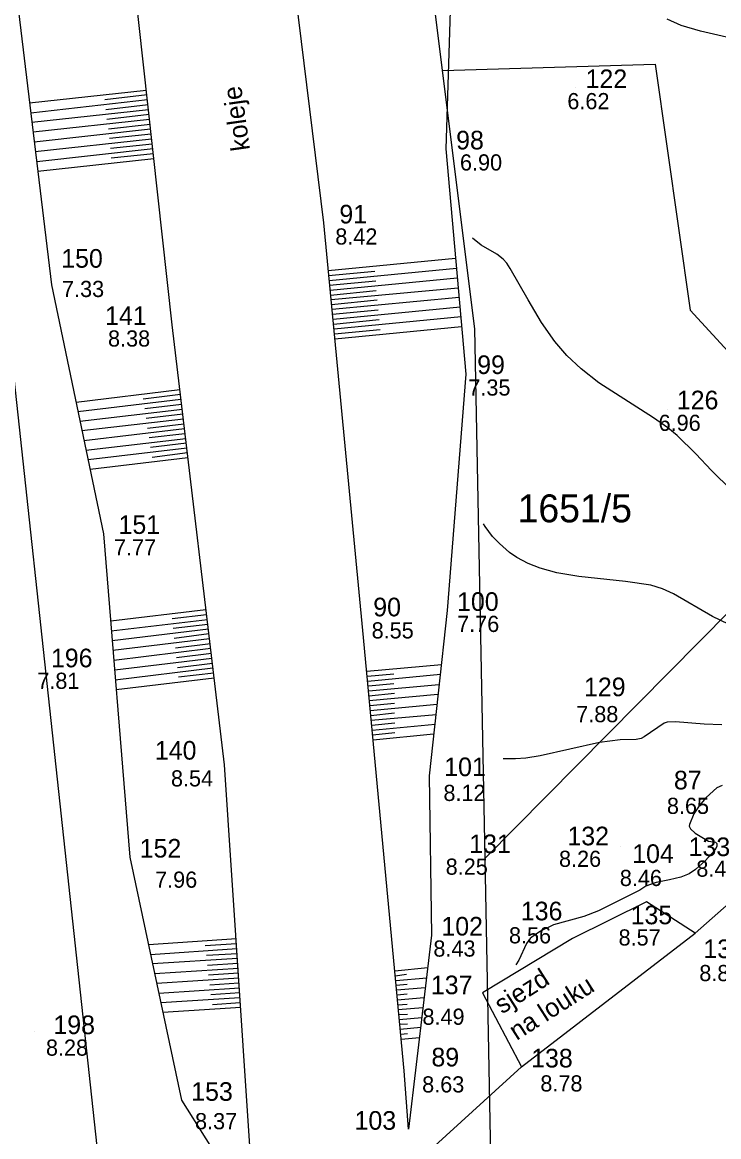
# Model space of a CAD drawing. Extents: x -792549 to -792339, y -1111914 to -1111617.
# Drawn here: x -792471.21 to -792457.02, y -1111705.97 to -1111683.25 of the extents above; entities that cross this region are included whole.
import ezdxf

# ---------------------------------------------------------------- set-up
doc = ezdxf.new("R2010")
doc.units = 0
for name, color, linetype in [('Vrstva 1', 7, 'Continuous'), ('Vrstva 32', 7, 'Continuous'), ('Vrstva 33', 7, 'Continuous'), ('Vrstva 41', 7, 'Continuous'), ('Vrstva 42', 7, 'Continuous'), ('Vrstva 45', 7, 'Continuous'), ('Vrstva 46', 7, 'Continuous'), ('Vrstva 48', 7, 'Continuous'), ('Vrstva 49', 7, 'Continuous'), ('Vrstva 50', 7, 'Continuous'), ('Vrstva 52', 7, 'Continuous'), ('Vrstva 54', 7, 'Continuous')]:
    doc.layers.add(name, color=color, linetype=linetype)

# ---------------------------------------------------------------- blocks, each defined once
blk = doc.blocks.new('SC6231')
at = {"layer": 'Vrstva 1'}
blk.add_line((0, 0), (0, 0), dxfattribs=at)

msp = doc.modelspace()

# ---------------------------------------------------------------- linework, layer by layer
at = {"layer": 'Vrstva 32'}
for points in [[(-792456.756, -1111692.789), (-792457.164, -1111692.387), (-792457.485, -1111692.05), (-792457.861, -1111691.674), (-792458.052, -1111691.514), (-792458.347, -1111691.313), (-792459.458, -1111690.601), (-792459.824, -1111690.317), (-792460.113, -1111690.042), (-792460.358, -1111689.755), (-792460.63, -1111689.369), (-792460.905, -1111688.91), (-792461.268, -1111688.265), (-792461.337, -1111688.156), (-792461.409, -1111688.076), (-792461.538, -1111687.979), (-792461.861, -1111687.792), (-792462.038, -1111687.652)], [(-792456.956, -1111697.572), (-792457.311, -1111697.56), (-792457.898, -1111697.511), (-792458.067, -1111697.521), (-792458.13, -1111697.541), (-792458.534, -1111697.815), (-792458.601, -1111697.849), (-792458.699, -1111697.869), (-792459.027, -1111697.876), (-792459.445, -1111697.931), (-792460.658, -1111698.206), (-792460.951, -1111698.252), (-792461.157, -1111698.268), (-792461.413, -1111698.265)]]:
    msp.add_lwpolyline(points, dxfattribs=at)
at = {"layer": 'Vrstva 33'}
for points in [[(-792456.593, -1111683.613), (-792457.386, -1111683.428), (-792457.783, -1111683.31), (-792458.07, -1111683.186)], [(-792456.816, -1111695.519), (-792457.146, -1111695.362), (-792457.939, -1111694.903), (-792458.164, -1111694.797), (-792458.402, -1111694.727), (-792458.915, -1111694.652), (-792459.87, -1111694.547), (-792460.314, -1111694.471), (-792460.66, -1111694.379), (-792460.904, -1111694.283), (-792461.135, -1111694.161), (-792461.28, -1111694.057), (-792461.486, -1111693.877), (-792461.626, -1111693.73), (-792461.781, -1111693.529), (-792461.811, -1111693.478)], [(-792456.944, -1111698.808), (-792457.052, -1111698.855), (-792457.273, -1111699.054), (-792457.416, -1111699.222), (-792457.522, -1111699.386), (-792457.615, -1111699.603), (-792457.617, -1111699.637), (-792457.592, -1111699.694), (-792457.499, -1111699.78), (-792457.226, -1111699.947), (-792457.08, -1111699.965), (-792457.057, -1111699.99), (-792457.052, -1111700.053), (-792457.099, -1111700.13), (-792457.293, -1111700.348), (-792457.487, -1111700.524), (-792457.618, -1111700.61), (-792457.787, -1111700.681), (-792458.023, -1111700.737), (-792458.289, -1111700.786), (-792458.503, -1111700.865), (-792458.623, -1111700.948), (-792459.467, -1111701.364), (-792459.765, -1111701.483), (-792460.385, -1111701.654), (-792460.651, -1111701.783), (-792460.83, -1111701.903), (-792460.859, -1111701.93), (-792460.936, -1111702.034), (-792461.09, -1111702.37), (-792461.153, -1111702.466)]]:
    msp.add_lwpolyline(points, dxfattribs=at)
at = {"layer": 'Vrstva 41'}
for points in [[(-792462.65, -1111684.23), (-792470.12, -1111624.156)], [(-792396.21, -1111631.51), (-792404.9, -1111639.66), (-792454.29, -1111692.72), (-792461.78, -1111700.29), (-792461.99, -1111689.5), (-792462.65, -1111684.23), (-792458.31, -1111684.1), (-792457.6, -1111689.12), (-792454.29, -1111692.72)], [(-792472.48, -1111680.42), (-792469.49, -1111708.06), (-792472.44, -1111711.74), (-792473.08, -1111699.31), (-792481.68, -1111682.99)], [(-792468.11, -1111720.8), (-792467.76, -1111724.02), (-792461.41, -1111719.58), (-792461.78, -1111700.29)]]:
    msp.add_lwpolyline(points, dxfattribs=at)
at = {"layer": 'Vrstva 46'}
for points in [[(-792466.48, -1111707.59), (-792467.09, -1111698.39), (-792468.16, -1111689.42), (-792468.94, -1111682.32), (-792469.82, -1111674.62), (-792470.64, -1111665.94), (-792471.65, -1111658.95)], [(-792474.58, -1111659.1), (-792474.14, -1111664.3), (-792473.03, -1111672.63), (-792471.62, -1111680.31), (-792470.62, -1111688.6), (-792469.56, -1111693.68), (-792469.02, -1111700.27), (-792467.97, -1111705.23), (-792466.48, -1111707.59)], [(-792464.38, -1111663.08), (-792463.28, -1111670.4), (-792462.69, -1111676.81), (-792462.46, -1111681.92), (-792462.58, -1111685.83), (-792462.17, -1111690.42), (-792462.55, -1111695.24), (-792462.92, -1111698.61), (-792462.87, -1111701.86), (-792463.34, -1111705.82)], [(-792463.34, -1111705.82), (-792463.43, -1111704.63), (-792464.27, -1111695.65), (-792465.07, -1111687.34), (-792466.27, -1111677.56), (-792467.145, -1111670.547), (-792468.021, -1111663.535)], [(-792457.5, -1111701.82), (-792458.49, -1111701.18), (-792460, -1111701.93), (-792461.83, -1111703.04), (-792461.04, -1111704.55)]]:
    msp.add_lwpolyline(points, dxfattribs=at)
at = {"layer": 'Vrstva 52'}
msp.add_line((-792461.04, -1111704.55), (-792457.5, -1111701.82), dxfattribs=at)
for points in [[(-792430.84, -1111675.46), (-792443.34, -1111688.31), (-792451.9, -1111696.88), (-792457.5, -1111701.82)], [(-792461.04, -1111704.55), (-792465.57, -1111708.68), (-792470.85, -1111713.69), (-792475, -1111717.97), (-792476.06, -1111719.06), (-792477.52, -1111721.33), (-792480.13, -1111725.28), (-792484.43, -1111732.17), (-792488.75, -1111739.76), (-792492.85, -1111746.66), (-792495.96, -1111751.8)]]:
    msp.add_lwpolyline(points, dxfattribs=at)
at = {"layer": 'Vrstva 54'}
for p, q in [((-792468.69, -1111684.64), (-792471.07, -1111684.9)), ((-792468.67, -1111684.73), (-792469.53, -1111684.83)), ((-792468.66, -1111684.83), (-792471.04, -1111685.1)), ((-792468.65, -1111684.93), (-792469.51, -1111685.03)), ((-792468.64, -1111685.03), (-792471.02, -1111685.29)), ((-792468.63, -1111685.13), (-792469.49, -1111685.23)), ((-792468.62, -1111685.23), (-792470.99, -1111685.49)), ((-792468.61, -1111685.33), (-792469.46, -1111685.43)), ((-792468.6, -1111685.43), (-792470.97, -1111685.69)), ((-792468.58, -1111685.63), (-792470.95, -1111685.89)), ((-792468.59, -1111685.53), (-792469.44, -1111685.62)), ((-792468.55, -1111685.83), (-792470.92, -1111686.09)), ((-792468.57, -1111685.73), (-792469.42, -1111685.82)), ((-792468.53, -1111686.03), (-792470.9, -1111686.29)), ((-792468.54, -1111685.93), (-792469.4, -1111686.02)), ((-792464.98, -1111688.31), (-792462.38, -1111688.06)), ((-792464.97, -1111688.41), (-792464.03, -1111688.32)), ((-792464.96, -1111688.51), (-792462.36, -1111688.26)), ((-792464.95, -1111688.61), (-792464.01, -1111688.52)), ((-792464.94, -1111688.71), (-792462.35, -1111688.46)), ((-792464.93, -1111688.81), (-792464, -1111688.72)), ((-792464.92, -1111688.9), (-792462.33, -1111688.66)), ((-792464.91, -1111689), (-792463.98, -1111688.91)), ((-792464.9, -1111689.1), (-792462.31, -1111688.85)), ((-792464.88, -1111689.3), (-792462.29, -1111689.05)), ((-792464.89, -1111689.2), (-792463.96, -1111689.11)), ((-792464.86, -1111689.5), (-792462.27, -1111689.25)), ((-792464.87, -1111689.4), (-792463.94, -1111689.31)), ((-792464.85, -1111689.6), (-792463.92, -1111689.51)), ((-792464.84, -1111689.7), (-792462.26, -1111689.45)), ((-792468, -1111690.74), (-792470.12, -1111691)), ((-792467.99, -1111690.84), (-792468.75, -1111690.93)), ((-792467.98, -1111690.94), (-792470.08, -1111691.19)), ((-792467.97, -1111691.04), (-792468.72, -1111691.13)), ((-792467.95, -1111691.14), (-792470.04, -1111691.39)), ((-792467.94, -1111691.24), (-792468.69, -1111691.33)), ((-792467.93, -1111691.34), (-792470, -1111691.58)), ((-792467.91, -1111691.54), (-792469.96, -1111691.78)), ((-792467.92, -1111691.44), (-792468.66, -1111691.53)), ((-792467.88, -1111691.74), (-792469.92, -1111691.98)), ((-792467.9, -1111691.64), (-792468.63, -1111691.72)), ((-792467.86, -1111691.93), (-792469.87, -1111692.17)), ((-792467.87, -1111691.83), (-792468.6, -1111691.92)), ((-792467.84, -1111692.13), (-792469.83, -1111692.37)), ((-792467.85, -1111692.03), (-792468.57, -1111692.12)), ((-792467.47, -1111695.23), (-792469.41, -1111695.46)), ((-792467.46, -1111695.33), (-792468.16, -1111695.41)), ((-792467.44, -1111695.43), (-792469.4, -1111695.66)), ((-792467.42, -1111695.62), (-792469.38, -1111695.86)), ((-792467.43, -1111695.53), (-792468.14, -1111695.61)), ((-792467.4, -1111695.82), (-792469.37, -1111696.06)), ((-792467.41, -1111695.72), (-792468.12, -1111695.81)), ((-792467.37, -1111696.02), (-792469.35, -1111696.26)), ((-792467.38, -1111695.92), (-792468.09, -1111696.01)), ((-792467.35, -1111696.22), (-792469.33, -1111696.46)), ((-792467.36, -1111696.12), (-792468.07, -1111696.21)), ((-792467.34, -1111696.32), (-792468.05, -1111696.41)), ((-792467.33, -1111696.42), (-792469.32, -1111696.66)), ((-792467.31, -1111696.52), (-792468.03, -1111696.6)), ((-792464.19, -1111696.48), (-792462.67, -1111696.34)), ((-792464.18, -1111696.58), (-792463.64, -1111696.53)), ((-792464.17, -1111696.68), (-792462.69, -1111696.54)), ((-792467.3, -1111696.62), (-792469.3, -1111696.86)), ((-792464.16, -1111696.78), (-792463.64, -1111696.73)), ((-792464.15, -1111696.88), (-792462.72, -1111696.75)), ((-792464.15, -1111696.98), (-792463.63, -1111696.93)), ((-792464.14, -1111697.08), (-792462.74, -1111696.95)), ((-792464.13, -1111697.18), (-792463.63, -1111697.13)), ((-792464.12, -1111697.28), (-792462.76, -1111697.15)), ((-792464.11, -1111697.38), (-792463.63, -1111697.33)), ((-792464.1, -1111697.48), (-792462.78, -1111697.36)), ((-792464.09, -1111697.58), (-792463.62, -1111697.53)), ((-792464.08, -1111697.68), (-792462.8, -1111697.56)), ((-792464.07, -1111697.78), (-792463.62, -1111697.73)), ((-792464.06, -1111697.88), (-792462.83, -1111697.76)), ((-792466.85, -1111701.94), (-792468.64, -1111702.06)), ((-792466.84, -1111702.14), (-792468.6, -1111702.26)), ((-792466.85, -1111702.04), (-792467.49, -1111702.08)), ((-792466.83, -1111702.24), (-792467.46, -1111702.28)), ((-792466.83, -1111702.34), (-792468.56, -1111702.45)), ((-792466.82, -1111702.44), (-792467.44, -1111702.48)), ((-792466.81, -1111702.54), (-792468.52, -1111702.65)), ((-792466.81, -1111702.64), (-792467.42, -1111702.68)), ((-792463.62, -1111702.59), (-792462.95, -1111702.52)), ((-792463.61, -1111702.69), (-792463.38, -1111702.66)), ((-792466.8, -1111702.74), (-792468.47, -1111702.85)), ((-792466.8, -1111702.84), (-792467.39, -1111702.88)), ((-792463.6, -1111702.79), (-792462.97, -1111702.73)), ((-792463.59, -1111702.88), (-792463.37, -1111702.86)), ((-792466.79, -1111702.94), (-792468.43, -1111703.05)), ((-792466.78, -1111703.14), (-792468.39, -1111703.24)), ((-792466.78, -1111703.04), (-792467.37, -1111703.08)), ((-792463.58, -1111702.98), (-792463, -1111702.93)), ((-792463.57, -1111703.08), (-792463.37, -1111703.06)), ((-792463.57, -1111703.18), (-792463.02, -1111703.13)), ((-792466.76, -1111703.34), (-792468.35, -1111703.44)), ((-792466.77, -1111703.24), (-792467.34, -1111703.28)), ((-792463.56, -1111703.28), (-792463.37, -1111703.27)), ((-792463.55, -1111703.38), (-792463.05, -1111703.34)), ((-792463.54, -1111703.48), (-792463.36, -1111703.47)), ((-792463.53, -1111703.58), (-792463.07, -1111703.54)), ((-792463.52, -1111703.68), (-792463.36, -1111703.67)), ((-792463.51, -1111703.78), (-792463.09, -1111703.74)), ((-792463.5, -1111703.88), (-792463.36, -1111703.87)), ((-792463.49, -1111703.98), (-792463.12, -1111703.95))]:
    msp.add_line(p, q, dxfattribs=at)

# ---------------------------------------------------------------- block references
at = {"layer": 'Vrstva 48', "xscale": 0.1, "yscale": 0.10000000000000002}
for p in [(-792459.93, -1111684.58), (-792462.58, -1111685.83), (-792465.07, -1111687.34), (-792470.62, -1111688.6), (-792468.16, -1111689.42), (-792462.17, -1111690.42), (-792458.07, -1111691.14), (-792469.56, -1111693.68), (-792462.55, -1111695.24), (-792464.27, -1111695.65), (-792470.83, -1111696.4), (-792458.57, -1111697.02), (-792467.09, -1111698.39), (-792462.92, -1111698.61), (-792462.41, -1111700.19), (-792459.02, -1111700.06), (-792469.02, -1111700.27), (-792457.47, -1111700.23), (-792458.51, -1111700.69), (-792458.49, -1111701.18), (-792462.87, -1111701.86), (-792460, -1111701.93), (-792457.5, -1111701.82), (-792461.83, -1111703.04), (-792470.97, -1111703.83), (-792463.43, -1111704.63), (-792461.04, -1111704.55), (-792467.97, -1111705.23), (-792463.34, -1111705.82)]:
    msp.add_blockref('SC6231', p, dxfattribs=at)

# ---------------------------------------------------------------- texts
at = {"layer": 'Vrstva 42'}
msp.add_text('1651/5', height=0.57, dxfattribs=at).set_placement((-792461.117, -1111693.444))
at = {"layer": 'Vrstva 45'}
for s, rotation, p in [('koleje', 97.9503, (-792466.571, -1111685.844)), ('sjezd', 32.5718, (-792461.434, -1111703.48)), ('na louku', 32.5718, (-792461.137, -1111704.019))]:
    msp.add_text(s, height=0.38, rotation=rotation, dxfattribs=at).set_placement(p)
at = {"layer": 'Vrstva 49'}
for s, p in [('122', (-792459.731, -1111684.59)), ('98', (-792462.37, -1111685.84)), ('91', (-792464.751, -1111687.35)), ('150', (-792470.421, -1111688.252)), ('141', (-792469.527, -1111689.42)), ('99', (-792461.941, -1111690.42)), ('126', (-792457.871, -1111691.14)), ('151', (-792469.253, -1111693.68)), ('100', (-792462.351, -1111695.25)), ('90', (-792464.06, -1111695.361)), ('196', (-792470.631, -1111696.4)), ('129', (-792459.763, -1111696.99)), ('140', (-792468.512, -1111698.283)), ('101', (-792462.613, -1111698.62)), ('87', (-792457.93, -1111698.89)), ('132', (-792460.101, -1111700.03)), ('152', (-792468.821, -1111700.28)), ('131', (-792462.103, -1111700.19)), ('133', (-792457.631, -1111700.25)), ('104', (-792458.78, -1111700.39)), ('136', (-792461.051, -1111701.56)), ('135', (-792458.813, -1111701.64)), ('102', (-792462.671, -1111701.87)), ('134', (-792457.33, -1111702.33)), ('137', (-792462.885, -1111703.066)), ('198', (-792470.581, -1111703.88)), ('89', (-792462.874, -1111704.539)), ('138', (-792460.841, -1111704.56)), ('153', (-792467.771, -1111705.24)), ('103', (-792464.441, -1111705.83))]:
    msp.add_text(s, height=0.38, dxfattribs=at).set_placement(p)
at = {"layer": 'Vrstva 50'}
for s, p in [('6.62', (-792460.103, -1111685.02)), ('6.90', (-792462.292, -1111686.27)), ('8.42', (-792464.834, -1111687.78)), ('7.33', (-792470.405, -1111688.85)), ('8.38', (-792469.467, -1111689.86)), ('7.35', (-792462.121, -1111690.86)), ('6.96', (-792458.243, -1111691.58)), ('7.77', (-792469.346, -1111694.12)), ('7.76', (-792462.35, -1111695.68)), ('8.55', (-792464.093, -1111695.812)), ('7.81', (-792470.909, -1111696.84)), ('7.88', (-792459.923, -1111697.52)), ('8.54', (-792468.184, -1111698.83)), ('8.12', (-792462.629, -1111699.126)), ('8.65', (-792458.073, -1111699.39)), ('8.26', (-792460.273, -1111700.47)), ('8.25', (-792462.583, -1111700.63)), ('8.45', (-792457.473, -1111700.67)), ('7.96', (-792468.508, -1111700.895)), ('8.46', (-792459.033, -1111700.86)), ('8.56', (-792461.293, -1111702.03)), ('8.57', (-792459.059, -1111702.074)), ('8.43', (-792462.834, -1111702.3)), ('8.80', (-792457.413, -1111702.8)), ('8.49', (-792463.057, -1111703.69)), ('8.28', (-792470.733, -1111704.32)), ('8.63', (-792463.063, -1111705.07)), ('8.78', (-792460.653, -1111705.05)), ('8.37', (-792467.693, -1111705.82))]:
    msp.add_text(s, height=0.33, dxfattribs=at).set_placement(p)

doc.saveas('drawing.dxf')
